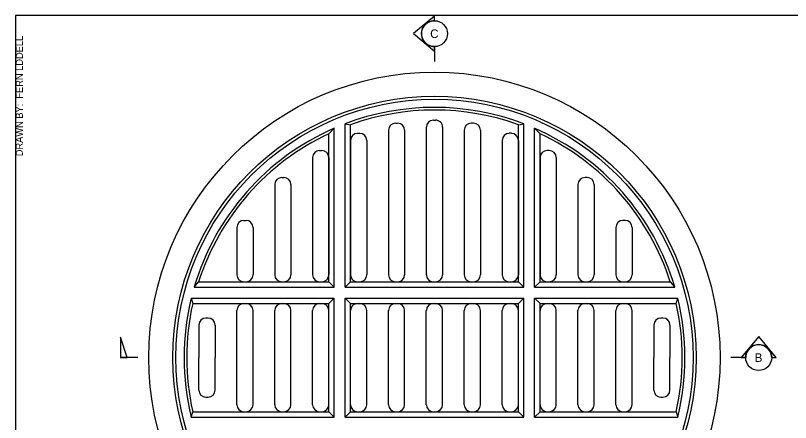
# Model space of a CAD drawing. Extents: x 99862 to 103151, y 100000 to 102076.
# Drawn here: x 99862 to 101651, y 101135 to 102076 of the extents above; entities that cross this region are included whole.
import ezdxf

# ---------------------------------------------------------------- set-up
doc = ezdxf.new("R2010")
doc.units = 0
for name, color, linetype in [('Level 1', 7, 'Continuous'), ('Level 18', 7, 'Continuous'), ('Level 20', 7, 'Continuous'), ('Level 62', 7, 'Continuous'), ('Level 9', 7, 'Continuous')]:
    doc.layers.add(name, color=color, linetype=linetype)

msp = doc.modelspace()

# ---------------------------------------------------------------- linework, layer by layer
at = {"layer": 'Level 1'}
msp.add_lwpolyline([(99862, 99999.5), (103151, 99999.5), (103151, 102075.5), (99862, 102075.5)], close=True, dxfattribs=at)
at = {"layer": 'Level 18'}
for p, q in [((100826.6, 101833.6), (100831.6, 101833.6)), ((100585.3, 101802.4), (100597.8, 101815)), ((100597.8, 101447.6), (100597.8, 101815)), ((100622.8, 101447.6), (100622.8, 101825.2)), ((100622.8, 101825.2), (100635.3, 101823.2)), ((100635.3, 101460.1), (100635.3, 101823.2)), ((100722.8, 101810.5), (100722.8, 101476.3)), ((100739.1, 101826.7), (100744.1, 101826.7)), ((100760.3, 101810.5), (100760.3, 101476.3)), ((100810.3, 101817.4), (100810.3, 101476.3)), ((100847.8, 101817.4), (100847.8, 101476.3)), ((100897.8, 101810.5), (100897.8, 101476.3)), ((100919.1, 101826.7), (100914.1, 101826.7)), ((100935.3, 101810.5), (100935.3, 101476.3)), ((101022.8, 101823.2), (101035.3, 101825.2)), ((101022.8, 101460.1), (101022.8, 101823.2)), ((101035.3, 101447.6), (101035.3, 101825.2)), ((101060.3, 101447.6), (101060.3, 101815)), ((101060.3, 101815), (101072.8, 101802.4)), ((100585.3, 101460.1), (100585.3, 101802.4)), ((100651.6, 101803.3), (100656.6, 101803.3)), ((101006.6, 101803.3), (101001.6, 101803.3)), ((101072.8, 101460.1), (101072.8, 101802.4)), ((100635.3, 101787), (100635.3, 101476.3)), ((100672.8, 101787), (100672.8, 101476.3)), ((100985.3, 101787), (100985.3, 101476.3)), ((101022.8, 101787), (101022.8, 101476.3)), ((100564.1, 101763.5), (100569.1, 101763.5)), ((101094.1, 101763.5), (101089.1, 101763.5)), ((100547.8, 101747.2), (100547.8, 101476.3)), ((100585.3, 101747.2), (100585.3, 101476.3)), ((101072.8, 101747.2), (101072.8, 101476.3)), ((101110.3, 101747.2), (101110.3, 101476.3)), ((100460.3, 101684.8), (100460.3, 101476.3)), ((100476.6, 101701.1), (100481.6, 101701.1)), ((100497.8, 101684.8), (100497.8, 101476.3)), ((101160.3, 101684.8), (101160.3, 101476.3)), ((101181.6, 101701.1), (101176.6, 101701.1)), ((101197.8, 101684.8), (101197.8, 101476.3)), ((100389.1, 101602.1), (100394.1, 101602.1)), ((101269.1, 101602.1), (101264.1, 101602.1)), ((100372.8, 101585.8), (100372.8, 101476.3)), ((100410.3, 101585.8), (100410.3, 101476.3)), ((101247.8, 101585.8), (101247.8, 101476.3)), ((101285.3, 101585.8), (101285.3, 101476.3)), ((100274.3, 101447.6), (100284.6, 101460.1)), ((100284.6, 101460.1), (100585.3, 101460.1)), ((100389.1, 101460.1), (100394.1, 101460.1)), ((100476.6, 101460.1), (100481.6, 101460.1)), ((100564.1, 101460.1), (100569.1, 101460.1)), ((100597.8, 101447.6), (100585.3, 101460.1)), ((100622.8, 101447.6), (100635.3, 101460.1)), ((100635.3, 101460.1), (101022.8, 101460.1)), ((100651.6, 101460.1), (100656.6, 101460.1)), ((100739.1, 101460.1), (100744.1, 101460.1)), ((100826.6, 101460.1), (100831.6, 101460.1)), ((100914.1, 101460.1), (100919.1, 101460.1)), ((101001.6, 101460.1), (101006.6, 101460.1)), ((101035.3, 101447.6), (101022.8, 101460.1)), ((101060.3, 101447.6), (101072.8, 101460.1)), ((101072.8, 101460.1), (101373.5, 101460.1)), ((101089.1, 101460.1), (101094.1, 101460.1)), ((101176.6, 101460.1), (101181.6, 101460.1)), ((101264.1, 101460.1), (101269.1, 101460.1)), ((101373.5, 101460.1), (101383.9, 101447.6)), ((100274.3, 101447.6), (100597.8, 101447.6)), ((100622.8, 101447.6), (101035.3, 101447.6)), ((101060.3, 101447.6), (101383.9, 101447.6)), ((100267.6, 101422.6), (100597.8, 101422.6)), ((100267.6, 101422.6), (100271, 101410.1)), ((100585.3, 101410.1), (100597.8, 101422.6)), ((100597.8, 101147.6), (100597.8, 101422.6)), ((100622.8, 101147.6), (100622.8, 101422.6)), ((100635.3, 101410.1), (100622.8, 101422.6)), ((100622.8, 101422.6), (101035.3, 101422.6)), ((101022.8, 101410.1), (101035.3, 101422.6)), ((101035.3, 101147.6), (101035.3, 101422.6)), ((101060.3, 101422.6), (101390.6, 101422.6)), ((101060.3, 101422.6), (101072.8, 101410.1)), ((101060.3, 101147.6), (101060.3, 101422.6)), ((101387.1, 101410.1), (101390.6, 101422.6)), ((100271, 101410.1), (100585.3, 101410.1)), ((100389.1, 101410.1), (100394.1, 101410.1)), ((100476.6, 101410.1), (100481.6, 101410.1)), ((100564.1, 101410.1), (100569.1, 101410.1)), ((100585.3, 101160.1), (100585.3, 101410.1)), ((100635.3, 101160.1), (100635.3, 101410.1)), ((100635.3, 101410.1), (101022.8, 101410.1)), ((100651.6, 101410.1), (100656.6, 101410.1)), ((100739.1, 101410.1), (100744.1, 101410.1)), ((100826.6, 101410.1), (100831.6, 101410.1)), ((100914.1, 101410.1), (100919.1, 101410.1)), ((101001.6, 101410.1), (101006.6, 101410.1)), ((101022.8, 101160.1), (101022.8, 101410.1)), ((101072.8, 101410.1), (101387.1, 101410.1)), ((101072.8, 101160.1), (101072.8, 101410.1)), ((101089.1, 101410.1), (101094.1, 101410.1)), ((101176.6, 101410.1), (101181.6, 101410.1)), ((101264.1, 101410.1), (101269.1, 101410.1)), ((100372.8, 101176.3), (100372.8, 101393.8)), ((100410.3, 101176.3), (100410.3, 101393.8)), ((100460.3, 101176.3), (100460.3, 101393.8)), ((100497.8, 101176.3), (100497.8, 101393.8)), ((100547.8, 101176.3), (100547.8, 101393.8)), ((100585.3, 101176.3), (100585.3, 101393.8)), ((100635.3, 101176.3), (100635.3, 101393.8)), ((100672.8, 101176.3), (100672.8, 101393.8)), ((100722.8, 101176.3), (100722.8, 101393.8)), ((100760.3, 101176.3), (100760.3, 101393.8)), ((100810.3, 101176.3), (100810.3, 101393.8)), ((100847.8, 101176.3), (100847.8, 101393.8)), ((100897.8, 101176.3), (100897.8, 101393.8)), ((100935.3, 101176.3), (100935.3, 101393.8)), ((100985.3, 101176.3), (100985.3, 101393.8)), ((101022.8, 101176.3), (101022.8, 101393.8)), ((101072.8, 101176.3), (101072.8, 101393.8)), ((101110.3, 101176.3), (101110.3, 101393.8)), ((101160.3, 101176.3), (101160.3, 101393.8)), ((101197.8, 101176.3), (101197.8, 101393.8)), ((101247.8, 101176.3), (101247.8, 101393.8)), ((101285.3, 101176.3), (101285.3, 101393.8)), ((100301.6, 101376.6), (100306.6, 101376.6)), ((101351.6, 101376.6), (101356.6, 101376.6)), ((100285.3, 101360.3), (100285.3, 101285.1)), ((100322.8, 101360.3), (100322.8, 101285.1)), ((101335.3, 101360.3), (101335.3, 101285.1)), ((101372.8, 101360.3), (101372.8, 101285.1)), ((100285.3, 101209.9), (100285.3, 101285.1)), ((100322.8, 101209.9), (100322.8, 101285.1)), ((101335.3, 101209.9), (101335.3, 101285.1)), ((101372.8, 101209.9), (101372.8, 101285.1)), ((100301.6, 101193.6), (100306.6, 101193.6)), ((101351.6, 101193.6), (101356.6, 101193.6)), ((100267.6, 101147.6), (100271, 101160.1)), ((100267.6, 101147.6), (100597.8, 101147.6)), ((100271, 101160.1), (100585.3, 101160.1)), ((100389.1, 101160.1), (100394.1, 101160.1)), ((100476.6, 101160.1), (100481.6, 101160.1)), ((100564.1, 101160.1), (100569.1, 101160.1)), ((100585.3, 101160.1), (100597.8, 101147.6)), ((100635.3, 101160.1), (100622.8, 101147.6)), ((100622.8, 101147.6), (101035.3, 101147.6)), ((100635.3, 101160.1), (101022.8, 101160.1)), ((100651.6, 101160.1), (100656.6, 101160.1)), ((100739.1, 101160.1), (100744.1, 101160.1)), ((100826.6, 101160.1), (100831.6, 101160.1)), ((100914.1, 101160.1), (100919.1, 101160.1)), ((101001.6, 101160.1), (101006.6, 101160.1)), ((101022.8, 101160.1), (101035.3, 101147.6)), ((101060.3, 101147.6), (101072.8, 101160.1)), ((101060.3, 101147.6), (101390.6, 101147.6)), ((101072.8, 101160.1), (101387.1, 101160.1)), ((101089.1, 101160.1), (101094.1, 101160.1)), ((101176.6, 101160.1), (101181.6, 101160.1)), ((101264.1, 101160.1), (101269.1, 101160.1)), ((101387.1, 101160.1), (101390.6, 101147.6))]:
    msp.add_line(p, q, dxfattribs=at)
for radius in [659.4, 603.8, 596.9]:
    msp.add_circle((100829.1, 101285.1), radius, dxfattribs=at)
for centre, radius, start, end in [((100829.1, 101285.1), 578.1, 69.0988, 110.9012), ((100829.1, 101285.1), 571.9, 70.1964, 109.8036), ((100826.6, 101817.4), 16.2, 90, 180), ((100831.6, 101817.4), 16.2, 359.9995, 90), ((100829.1, 101285.1), 578.1, 113.5782, 163.6753), ((100739.1, 101810.5), 16.2, 90, 180), ((100744.1, 101810.5), 16.2, 0, 90), ((100914.1, 101810.5), 16.2, 90, 180), ((100919.1, 101810.5), 16.2, 0, 90), ((100829.1, 101285.1), 578.1, 16.3247, 66.4218), ((100829.1, 101285.1), 571.9, 115.2285, 162.181), ((100651.6, 101787), 16.2, 90, 180), ((100656.6, 101787), 16.2, 0, 90), ((101001.6, 101787), 16.2, 90, 180), ((101006.6, 101787), 16.2, 0, 90), ((100829.1, 101285.1), 571.9, 17.819, 64.7715), ((100564.1, 101747.2), 16.2, 90, 180), ((100569.1, 101747.2), 16.2, 0, 90), ((101089.1, 101747.2), 16.2, 90, 180), ((101094.1, 101747.2), 16.2, 0, 90), ((100476.6, 101684.8), 16.2, 90, 180), ((100481.6, 101684.8), 16.2, 0, 90), ((101176.6, 101684.8), 16.2, 90, 180), ((101181.6, 101684.8), 16.2, 0, 90), ((100389.1, 101585.8), 16.2, 90, 180), ((100394.1, 101585.8), 16.2, 0, 90), ((101264.1, 101585.8), 16.2, 90, 180), ((101269.1, 101585.8), 16.2, 0, 90), ((100389.1, 101476.3), 16.2, 180, 270), ((100394.1, 101476.3), 16.2, 270, 0), ((100476.6, 101476.3), 16.2, 180, 270), ((100481.6, 101476.3), 16.2, 270, 0), ((100564.1, 101476.3), 16.2, 180, 270), ((100569.1, 101476.3), 16.2, 270, 0), ((100651.6, 101476.3), 16.2, 180, 270), ((100656.6, 101476.3), 16.2, 270, 0), ((100739.1, 101476.3), 16.2, 180, 270), ((100744.1, 101476.3), 16.2, 270, 0), ((100826.6, 101476.3), 16.2, 180, 270), ((100831.6, 101476.3), 16.2, 270, 0), ((100914.1, 101476.3), 16.2, 180, 270), ((100919.1, 101476.3), 16.2, 270, 0), ((101001.6, 101476.3), 16.2, 180, 270), ((101006.6, 101476.3), 16.2, 270, 0), ((101089.1, 101476.3), 16.2, 180, 270), ((101094.1, 101476.3), 16.2, 270, 0), ((101176.6, 101476.3), 16.2, 180, 270), ((101181.6, 101476.3), 16.2, 270, 0), ((101264.1, 101476.3), 16.2, 180, 270), ((101269.1, 101476.3), 16.2, 270, 0), ((100829.1, 101285.1), 578.1, 166.241, 193.759), ((100829.1, 101285.1), 578.1, 346.241, 13.759), ((100829.1, 101285.1), 571.9, 167.3744, 192.6256), ((100389.1, 101393.8), 16.2, 90, 180), ((100394.1, 101393.8), 16.2, 0, 90), ((100476.6, 101393.8), 16.2, 90, 180), ((100481.6, 101393.8), 16.2, 0, 90), ((100564.1, 101393.8), 16.2, 90, 180), ((100569.1, 101393.8), 16.2, 0, 90), ((100651.6, 101393.8), 16.2, 90, 180), ((100656.6, 101393.8), 16.2, 0, 90), ((100739.1, 101393.8), 16.2, 90, 180), ((100744.1, 101393.8), 16.2, 0, 90), ((100826.6, 101393.8), 16.2, 90, 180), ((100831.6, 101393.8), 16.2, 0, 90), ((100914.1, 101393.8), 16.2, 90, 180), ((100919.1, 101393.8), 16.2, 0, 90), ((101001.6, 101393.8), 16.2, 90, 180), ((101006.6, 101393.8), 16.2, 0, 90), ((101089.1, 101393.8), 16.2, 90, 180), ((101094.1, 101393.8), 16.2, 0, 90), ((101176.6, 101393.8), 16.2, 90, 180), ((101181.6, 101393.8), 16.2, 0, 90), ((101264.1, 101393.8), 16.2, 90, 180), ((101269.1, 101393.8), 16.2, 0, 90), ((100829.1, 101285.1), 571.9, 347.3744, 12.6256), ((100301.6, 101360.3), 16.2, 90, 180), ((100306.6, 101360.3), 16.2, 0, 90), ((101351.6, 101360.3), 16.2, 90, 180), ((101356.6, 101360.3), 16.2, 0, 90), ((100301.6, 101209.9), 16.2, 180, 270), ((100306.6, 101209.9), 16.2, 270, 0), ((101351.6, 101209.9), 16.2, 180, 270), ((101356.6, 101209.9), 16.2, 270, 0), ((100389.1, 101176.3), 16.2, 180, 270), ((100394.1, 101176.3), 16.2, 270, 0), ((100476.6, 101176.3), 16.2, 180, 270), ((100481.6, 101176.3), 16.2, 270, 0), ((100564.1, 101176.3), 16.2, 180, 270), ((100569.1, 101176.3), 16.2, 270, 0), ((100651.6, 101176.3), 16.2, 180, 270), ((100656.6, 101176.3), 16.2, 270, 0), ((100739.1, 101176.3), 16.2, 180, 270), ((100744.1, 101176.3), 16.2, 270, 0), ((100826.6, 101176.3), 16.2, 180, 270), ((100831.6, 101176.3), 16.2, 270, 0), ((100914.1, 101176.3), 16.2, 180, 270), ((100919.1, 101176.3), 16.2, 270, 0), ((101001.6, 101176.3), 16.2, 180, 270), ((101006.6, 101176.3), 16.2, 270, 0), ((101089.1, 101176.3), 16.2, 180, 270), ((101094.1, 101176.3), 16.2, 270, 0), ((101176.6, 101176.3), 16.2, 180, 270), ((101181.6, 101176.3), 16.2, 270, 0), ((101264.1, 101176.3), 16.2, 180, 270), ((101269.1, 101176.3), 16.2, 270, 0)]:
    msp.add_arc(centre, radius, start, end, dxfattribs=at)
at = {"layer": 'Level 9'}
for p, q in [((100829.1, 102074.1), (100780.6, 102033.5)), ((100829.1, 102063.5), (100829.1, 102074.1)), ((100780.6, 102033.5), (100829.1, 101992.9)), ((100829.1, 101992.9), (100829.1, 102003.5)), ((100829.1, 102003.5), (100829.1, 101969.5)), ((101577.5, 101333.6), (101536.9, 101285.1)), ((101618.1, 101285.1), (101577.5, 101333.6)), ((100144.7, 101285.1), (100104.2, 101285.1)), ((101547.5, 101285.1), (101513.5, 101285.1)), ((101536.9, 101285.1), (101547.5, 101285.1)), ((101607.5, 101285.1), (101618.1, 101285.1))]:
    msp.add_line(p, q, dxfattribs=at)
msp.add_lwpolyline([(100119.7, 101285.1), (100104.2, 101332), (100104.2, 101285.1)], close=True, dxfattribs=at)
for centre in [(100829.1, 102033.5), (101577.5, 101285.1)]:
    msp.add_circle(centre, 30, dxfattribs=at)
for centre, start, end in [((100829.1, 102033.5), 89.9978, 270.0022), ((101577.5, 101285.1), 359.9978, 180.0022)]:
    msp.add_arc(centre, 30, start, end, dxfattribs=at)

# ---------------------------------------------------------------- texts
at = {"layer": 'Level 20'}
msp.add_text('C', height=20, dxfattribs=at).set_placement((100819.2, 102023.4))
msp.add_text('B', height=20, rotation=360, dxfattribs=at).set_placement((101568.2, 101275.1))
at = {"layer": 'Level 62'}
msp.add_text('DRAWN BY:  FERN LDDELL', height=16, rotation=90, dxfattribs=at).set_placement((99879, 101750.3))

doc.saveas('drawing.dxf')
